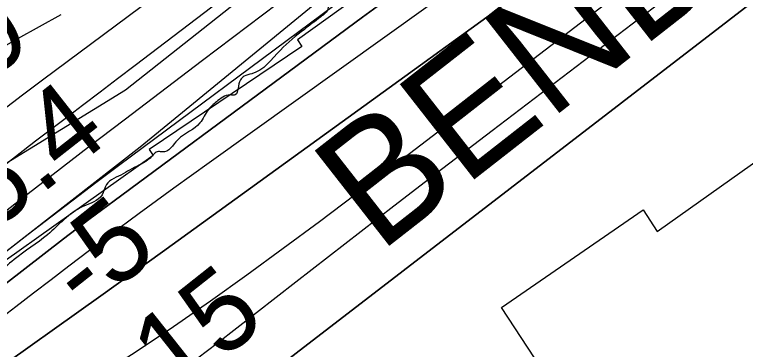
# Model space of a CAD drawing. Extents: x 3324104 to 3361979, y 612876 to 638273.
# Drawn here: x 3350527 to 3351130, y 619181 to 619458 of the extents above; entities that cross this region are included whole.
import ezdxf

# ---------------------------------------------------------------- set-up
doc = ezdxf.new("R2010")
doc.units = 0
for name, color, linetype in [('V-RIVR-EDGE', 7, 'Continuous'), ('V-RIVR-RANG', 7, 'Continuous'), ('V-RRAP-FSHR', 7, 'Continuous'), ('V-RRAP-RVMT', 7, 'Continuous'), ('V-RRAP-RVMT-IDEN', 7, 'Continuous'), ('V-TOPO-DPTH', 7, 'Continuous'), ('V-TOPO-MINR', 7, 'Continuous'), ('V-TOPO-WATR', 7, 'Continuous'), ('V-WETL-SWMP', 7, 'Continuous')]:
    doc.layers.add(name, color=color, linetype=linetype)

msp = doc.modelspace()

# ---------------------------------------------------------------- linework, layer by layer
at = {"layer": 'V-RIVR-EDGE'}
msp.add_spline([(3356051.95, 622889.63), (3356029.15, 622881.43), (3356012.46, 622875.66), (3355994.6, 622867.17), (3355977.52, 622859.07), (3355958.5, 622850.97), (3355948.4, 622843.24), (3355934.03, 622834.75), (3355904.12, 622817.76), (3355878.1, 622802.31), (3355856.74, 622790.34), (3355829.95, 622776.44), (3355805.11, 622765.65), (3355764.72, 622744.81), (3355744.14, 622733.61), (3355694.06, 622710.85), (3355668.43, 622698.12), (3355641.64, 622685), (3355605.15, 622669.19), (3355569.44, 622657.26), (3355539.17, 622646.47), (3355510.83, 622636.85), (3355482.11, 622628.39), (3355461.93, 622623.01), (3355442.52, 622614.14), (3355422.73, 622607.21), (3355409.53, 622603.36), (3355388.97, 622597.59), (3355371.88, 622589.49), (3355348.98, 622581.02), (3355297.71, 622547.02), (3355260.04, 622525.78), (3355211.1, 622494.49), (3355190.13, 622484.46), (3355184.7, 622482.92), (3355179.26, 622477.89), (3355174.21, 622475.58), (3355160.62, 622470.96), (3355143.54, 622463.63), (3355133.06, 622457.07), (3355125.67, 622450.49), (3355113.25, 622443.93), (3355096.93, 622433.11), (3355081.02, 622426.95), (3355064.32, 622419.23), (3355056.95, 622418.86), (3355048.8, 622414.62), (3355041.8, 622406.88), (3355036.76, 622406.5), (3355031.32, 622405.74), (3355027.05, 622404.2), (3355017.34, 622396.08), (3355010.74, 622394.93), (3355001.42, 622388.36), (3354988.6, 622379.09), (3354972.29, 622369.43), (3354947.44, 622356.31), (3354937.73, 622351.68), (3354926.08, 622343.56), (3354903.15, 622326.56), (3354891.11, 622318.06), (3354883.33, 622307.22), (3354879.44, 622304.12), (3354875.17, 622302.58), (3354867.8, 622299.11), (3354853.03, 622288.29), (3354842.54, 622279.01), (3354826.61, 622267.41), (3354807.2, 622259.71), (3354793.23, 622255.47), (3354765.68, 622249.73), (3354748.61, 622245.5), (3354734.63, 622239.33), (3354712.11, 622227.37), (3354697.74, 622218.87), (3354685.31, 622209.98), (3354640.65, 622184.5), (3354622.01, 622176.01), (3354616.19, 622175.25), (3354603.38, 622167.52), (3354578.92, 622157.11), (3354554.46, 622147.48), (3354537.39, 622142.87), (3354530.78, 622137.84), (3354500.11, 622122.79), (3354463.61, 622102.33), (3354417.79, 622078.79), (3354386.33, 622060.64), (3354340.11, 622032.44), (3354321.08, 622021.25), (3354284.96, 621998.84), (3354257, 621982.24), (3354217, 621958.68), (3354194.08, 621942.84), (3354176.99, 621931.63), (3354157.57, 621921.98), (3354141.64, 621910.39), (3354135.42, 621904.2), (3354130.36, 621897.62), (3354120.65, 621891.05), (3354103.96, 621882.95), (3354075.58, 621856.65), (3354044.89, 621835.39), (3354013.04, 621812.21), (3353971.47, 621781.67), (3353947.77, 621763.5), (3353941.17, 621763.52), (3353935.35, 621762.76), (3353929.53, 621760.06), (3353924.87, 621756.58), (3353920.59, 621751.55), (3353917.08, 621742.64), (3353910.48, 621741.49), (3353904.66, 621738.4), (3353893.78, 621731.06), (3353879.8, 621721.4), (3353866.19, 621708.64), (3353854.92, 621697.42), (3353843.26, 621687.75), (3353839.77, 621688.54), (3353831.23, 621686.23), (3353823.08, 621681.21), (3353818.03, 621677.34), (3353800.94, 621666.14), (3353790.85, 621663.06), (3353781.91, 621654.94), (3353777.63, 621651.85), (3353776.07, 621648.75), (3353775.67, 621643.71), (3353772.18, 621641), (3353755.87, 621632.13), (3353735.68, 621622.09), (3353718.58, 621608.17), (3353704.21, 621600.45), (3353694.12, 621596.6), (3353683.64, 621592.36), (3353671.21, 621584.25), (3353642.07, 621562.99), (3353598.95, 621534.01), (3353578.37, 621522.43), (3353556.23, 621507.75), (3353547.68, 621501.95), (3353525.93, 621489.21), (3353513.12, 621481.09), (3353497.18, 621468.34), (3353476.98, 621450.94), (3353453.28, 621436.65), (3353435.8, 621424.67), (3353404.72, 621401.09), (3353378.3, 621380.21), (3353361.59, 621368.62), (3353339.46, 621355.1), (3353319.65, 621342.35), (3353299.45, 621329.99), (3353283.54, 621324.6), (3353273.05, 621317.65), (3353254.77, 621295.98), (3353236.88, 621275.47), (3353219.39, 621258.83), (3353195.69, 621241.44), (3353168.49, 621221.34), (3353137.81, 621201.64), (3353112.17, 621185.03), (3353065.55, 621151.79), (3353022.05, 621122.82), (3352993.29, 621100.39), (3352956, 621073.34), (3352907.05, 621037.78), (3352853.8, 620991.77), (3352787.76, 620942.29), (3352749.68, 620913.3), (3352736.85, 620900.92), (3352733.34, 620892.79), (3352728.67, 620886.59), (3352718.96, 620881.19), (3352691.78, 620864.58), (3352660.31, 620841.78), (3352640.5, 620828.25), (3352623.39, 620811.23), (3352605.12, 620792.27), (3352593.46, 620783), (3352582.59, 620778.76), (3352566.29, 620771.43), (3352548.04, 620764.49), (3352522.41, 620750.98), (3352494.45, 620735.54), (3352482.41, 620727.04), (3352479.3, 620723.17), (3352476.96, 620717.36), (3352470.74, 620711.94), (3352455.99, 620707.33), (3352443.18, 620700.38), (3352419.1, 620685.7), (3352392.3, 620669.09), (3352362.78, 620650.94), (3352339.08, 620634.32), (3352315.38, 620615.38), (3352284.68, 620590.63), (3352258.65, 620571.31), (3352228.74, 620550.05), (3352193.39, 620527.65), (3352156.88, 620504.86), (3352131.63, 620487.47), (3352093.95, 620462.36), (3352049.28, 620432.99), (3351990.23, 620391.26), (3351936.63, 620357.26), (3351851.55, 620293.87), (3351833.29, 620281.51), (3351816.98, 620273.79), (3351794.06, 620257.95), (3351767.65, 620240.95), (3351719.86, 620206.17), (3351680.63, 620177.57), (3351657.32, 620160.56), (3351637.11, 620145.87), (3351623.13, 620135.44), (3351603.32, 620124.24), (3351588.57, 620120.01), (3351567.22, 620109.59), (3351552.08, 620103.43), (3351538.1, 620096.48), (3351523.73, 620086.43), (3351510.91, 620076.38), (3351503.52, 620069.81), (3351495.35, 620057.42), (3351486, 620042.32), (3351479.39, 620032.64), (3351469.67, 620022.58), (3351448.3, 620006.34), (3351431.59, 619994.75), (3351404.78, 619973.88), (3351377.97, 619951.84), (3351358.93, 619936.37), (3351332.12, 619915.5), (3351306.08, 619892.29), (3351274.58, 619858.25), (3351238.83, 619826.92), (3351215.12, 619805.65), (3351171.59, 619767.75), (3351145.54, 619739.51), (3351124.55, 619722.11), (3351105.9, 619707.81), (3351089.59, 619696.99), (3351079.49, 619691.2), (3351074.04, 619683.45), (3351058.1, 619666.43), (3351043.34, 619655.22), (3351015.36, 619633.96), (3350999.05, 619623.14), (3350992.05, 619617.34), (3350979.23, 619606.13), (3350966.01, 619594.53), (3350951.25, 619582.15), (3350935.7, 619567.84), (3350923.26, 619555.08), (3350910.05, 619544.25), (3350888.29, 619528.02), (3350846.74, 619504.08), (3350821.49, 619490.18), (3350811.39, 619483.61), (3350805.96, 619480.52), (3350800.9, 619473.16), (3350797.41, 619473.17), (3350793.92, 619474.35), (3350788.88, 619473.58), (3350786.93, 619472.04), (3350785.37, 619467.39), (3350785.36, 619462.73), (3350779.53, 619456.15), (3350765.93, 619445.72), (3350746.11, 619428.7), (3350722.4, 619408.98), (3350716.19, 619407.06), (3350713.08, 619403.96), (3350711.13, 619396.99), (3350708.79, 619391.57), (3350704.52, 619391.58), (3350693.26, 619385.79), (3350686.65, 619379.6), (3350679.64, 619368.37), (3350661.38, 619354.45), (3350648.56, 619344.4), (3350645.46, 619344.8), (3350638.47, 619339.39), (3350623.32, 619330.5), (3350616.33, 619326.26), (3350602.35, 619317.37), (3350598.83, 619308.85), (3350582.91, 619299.19), (3350553.77, 619276), (3350526.18, 619255.51), (3350493.55, 619231.94), (3350474.9, 619219.57), (3350474.5, 619213.76), (3350470.22, 619207.17), (3350458.96, 619202.55), (3350446.14, 619194.05), (3350441.09, 619189.79), (3350438.76, 619186.31), (3350434.48, 619180.89), (3350414.67, 619167.76), (3350401.46, 619159.26), (3350384.75, 619146.89), (3350369.6, 619133.74), (3350356.39, 619125.24), (3350350.95, 619119.05), (3350347.43, 619109.36), (3350338.1, 619097.75), (3350324.88, 619083.82), (3350308.55, 619069.9), (3350300.39, 619062.56), (3350296.13, 619062.57), (3350291.47, 619062.19), (3350274.77, 619050.6), (3350258.45, 619037.45), (3350251.84, 619032.81), (3350244.08, 619029.34), (3350233.61, 619028.21), (3350227.39, 619024.34), (3350220.39, 619016.99), (3350213, 619007.32), (3350202.12, 618996.87), (3350193.57, 618989.52), (3350179.6, 618985.29), (3350173.77, 618980.65), (3350164.84, 618977.96), (3350162.12, 618975.25), (3350159.39, 618971.38), (3350154.33, 618963.64), (3350145.78, 618953.19), (3350125.96, 618938.11), (3350102.66, 618923.05), (3350094.5, 618918.41), (3350086.34, 618913), (3350075.07, 618901.01), (3350064.19, 618892.12), (3350039.32, 618873.57), (3350021.84, 618861.59), (3350002.03, 618848.84), (3349991.94, 618844.21), (3349964.36, 618826.44), (3349938.72, 618807.11), (3349915.41, 618792.82), (3349892.5, 618778.92), (3349868.02, 618761.91), (3349852.49, 618753.03), (3349842.79, 618749.95), (3349830.35, 618739.13), (3349804.32, 618720.19), (3349777.9, 618697.76), (3349751.86, 618677.66), (3349729.72, 618661.43), (3349703.69, 618642.88), (3349678.84, 618629.75), (3349648.93, 618611.99), (3349624.46, 618594.99), (3349592.61, 618575.67), (3349570.48, 618564.87), (3349549.5, 618548.63), (3349505.21, 618518.11), (3349479.19, 618499.94), (3349471.42, 618494.53), (3349458.99, 618487.59), (3349438.4, 618472.12), (3349412.37, 618452.41), (3349379.73, 618429.61), (3349350.21, 618410.29), (3349303.2, 618374.73), (3349277.56, 618357.73), (3349263.97, 618347.29), (3349241.43, 618330.68), (3349226.67, 618319.85), (3349207.25, 618306.33), (3349193.17, 618293.54)], degree=3, dxfattribs=at)
at = {"layer": 'V-RRAP-FSHR'}
msp.add_lwpolyline([(3349156.55, 618293.48), (3349290.84, 618378.98), (3349409.37, 618477.79), (3349541.25, 618565.26), (3349771.64, 618715.9), (3349922.45, 618808.45), (3350215.79, 619019.76), (3350269.12, 619069.35), (3350501.35, 619248.31), (3350630.24, 619348.58), (3350981.59, 619636.83), (3351335.34, 619937.32), (3351550.69, 620108.65), (3351713.66, 620224.46), (3351812.36, 620304.63), (3352053.37, 620458.3), (3352414.71, 620728.03), (3352590.48, 620825.76), (3352682.34, 620894.14), (3352964.07, 621108.39), (3353211.76, 621284.79), (3354078.79, 621880.27)], dxfattribs=at)
at = {"layer": 'V-RRAP-RVMT'}
for p, q in [((3350883.62, 619526.25), (3350760.32, 619437.08)), ((3350760.32, 619437.08), (3350763.97, 619431.57)), ((3350763.97, 619431.57), (3350637.61, 619346.46)), ((3351057.33, 619278.7), (3351187.65, 619371.34)), ((3350637.61, 619346.46), (3350641.14, 619341.39)), ((3350641.14, 619341.39), (3350517.87, 619253.93)), ((3350928.77, 619215.7), (3351045.8, 619296.63)), ((3351045.8, 619296.63), (3351057.33, 619278.7)), ((3350956.08, 619174.07), (3350928.77, 619215.7))]:
    msp.add_line(p, q, dxfattribs=at)
at = {"layer": 'V-TOPO-DPTH'}
for points in [[(3350500.92, 619156.58), (3350597.73, 619225.34), (3350610.48, 619234.42), (3350623.21, 619243.52), (3350635.92, 619252.67), (3350648.6, 619261.84), (3350950.63, 619480.72), (3350989.67, 619509.08), (3351028.67, 619537.5), (3351067.61, 619566.01), (3351106.5, 619594.57), (3351173.35, 619643.79), (3351178.79, 619647.79), (3351184.23, 619651.79), (3351189.67, 619655.78), (3351195.12, 619659.76), (3351280.51, 619722.16), (3351328.59, 619757.43), (3351376.59, 619792.82), (3351424.45, 619828.38), (3351472.23, 619864.06), (3351729.95, 620057.28), (3351738.1, 620063.46)], [(3351738.1, 620063.46), (3351729.95, 620057.28), (3351472.23, 619864.06), (3351424.45, 619828.38), (3351376.59, 619792.82), (3351328.59, 619757.43), (3351280.51, 619722.16), (3351195.12, 619659.76), (3351189.67, 619655.78), (3351184.23, 619651.79), (3351178.79, 619647.79), (3351173.35, 619643.79), (3351106.5, 619594.57), (3351067.61, 619566.01), (3351028.67, 619537.5), (3350989.67, 619509.08), (3350950.63, 619480.72), (3350648.6, 619261.84), (3350635.92, 619252.67), (3350623.21, 619243.52), (3350610.48, 619234.42), (3350597.73, 619225.34), (3350500.92, 619156.58)], [(3351793.38, 619988), (3351727.81, 619942.08), (3351689.08, 619915.01), (3351650.31, 619887.99), (3351611.5, 619861.05), (3351572.65, 619834.15), (3351261.99, 619619.54), (3351244.52, 619607.29), (3351227.16, 619594.86), (3351209.99, 619582.2), (3351192.93, 619569.36), (3350921.06, 619361.8), (3350880.42, 619330.68), (3350839.84, 619299.48), (3350799.34, 619268.16), (3350758.91, 619236.77), (3350693.86, 619186.11), (3350685.96, 619180.04), (3350678, 619174.03), (3350669.98, 619168.12), (3350661.9, 619162.28), (3350597.95, 619116.62), (3350557.59, 619088.4), (3350516.88, 619060.72)], [(3351793.38, 619988), (3351727.81, 619942.08), (3351689.08, 619915.01), (3351650.31, 619887.99), (3351611.5, 619861.05), (3351572.65, 619834.15), (3351261.99, 619619.54), (3351244.52, 619607.29), (3351227.16, 619594.86), (3351209.99, 619582.2), (3351192.93, 619569.36), (3350921.06, 619361.8), (3350880.42, 619330.68), (3350839.84, 619299.48), (3350799.34, 619268.16), (3350758.91, 619236.77), (3350693.86, 619186.11), (3350685.96, 619180.04), (3350678, 619174.03), (3350669.98, 619168.12), (3350661.9, 619162.28), (3350597.95, 619116.62), (3350557.59, 619088.4), (3350516.88, 619060.72)], [(3350395.02, 618900.32), (3350654.07, 619097.36), (3350680.42, 619117.45), (3350706.75, 619137.57), (3350733.03, 619157.75), (3350759.29, 619177.96), (3351204.77, 619521.59), (3351212.95, 619527.9), (3351221.15, 619534.2), (3351229.35, 619540.49), (3351237.56, 619546.77), (3351245.83, 619552.97), (3351254.18, 619559.06), (3351262.63, 619565), (3351271.17, 619570.83), (3351275.85, 619573.96), (3351286.77, 619581.29), (3351297.7, 619588.61), (3351308.62, 619595.94), (3351319.54, 619603.27), (3351781.82, 619913.5)], [(3350686.93, 619122.42), (3350706.75, 619137.57), (3350733.03, 619157.75), (3350759.29, 619177.96), (3351204.77, 619521.59), (3351212.95, 619527.9), (3351221.15, 619534.2), (3351229.35, 619540.49), (3351237.56, 619546.77), (3351245.83, 619552.97), (3351254.18, 619559.06), (3351262.63, 619565), (3351271.17, 619570.83), (3351275.85, 619573.96), (3351286.77, 619581.29), (3351297.7, 619588.61), (3351308.62, 619595.94), (3351319.54, 619603.27), (3351781.82, 619913.5)], [(3351138.82, 619767.79), (3351112.25, 619747.19), (3351085.59, 619726.7), (3351058.86, 619706.3), (3350929.33, 619607.82), (3350867.49, 619560.83), (3350805.64, 619513.85), (3350743.78, 619466.88), (3350681.91, 619419.93), (3350616.98, 619370.66), (3350587.62, 619348.28), (3350558.34, 619325.79), (3350529.16, 619303.17), (3350500.06, 619280.45)], [(3350452.43, 619183.86), (3350567.04, 619272.57), (3350577.39, 619280.53), (3350587.78, 619288.45), (3350598.22, 619296.29), (3350608.7, 619304.1), (3350747.32, 619406.64), (3350813.93, 619455.73), (3350880.66, 619504.68), (3350947.55, 619553.39), (3351014.55, 619601.95), (3351126.37, 619682.68), (3351137.53, 619690.79)], [(3350452.43, 619183.86), (3350567.04, 619272.57), (3350577.39, 619280.53), (3350587.78, 619288.45), (3350598.22, 619296.29), (3350608.7, 619304.1), (3350747.32, 619406.64), (3350813.93, 619455.73), (3350880.66, 619504.68), (3350947.55, 619553.39), (3351014.55, 619601.95), (3351126.37, 619682.68), (3351137.53, 619690.79)]]:
    msp.add_lwpolyline(points, dxfattribs=at)
at = {"layer": 'V-TOPO-MINR'}
for points in [[(3351976.54, 620483.42), (3351682.77, 620260.49), (3351654.84, 620239.27), (3351626.94, 620218.02), (3351599.06, 620196.74), (3351571.2, 620175.44), (3351141.24, 619846.18), (3351130.29, 619837.79), (3351119.35, 619829.4), (3351108.4, 619821), (3351097.46, 619812.6), (3351080.44, 619799.52), (3351078.01, 619797.66), (3351075.57, 619795.81), (3351073.13, 619793.96), (3351070.68, 619792.13), (3351038.59, 619768.12), (3351020.09, 619754.29), (3351001.59, 619740.46), (3350983.07, 619726.65), (3350964.55, 619712.85), (3350549.5, 619403.67), (3350533.02, 619391.24), (3350516.63, 619378.69)], [(3351747.23, 620194.54), (3351715.65, 620170.75), (3351684.14, 620146.86), (3351652.76, 620122.82), (3351621.44, 620098.67), (3351144.46, 619728.99), (3351142.51, 619727.48), (3351140.56, 619725.99), (3351136.65, 619723.01), (3351133.13, 619720.35), (3351132.32, 619719.75), (3351131.91, 619719.45), (3351127.59, 619716.3), (3351125.02, 619714.42), (3351122.46, 619712.54), (3351119.9, 619710.65), (3351117.34, 619708.76), (3350612.45, 619332.91), (3350593.69, 619318.84), (3350574.98, 619304.68), (3350556.37, 619290.4), (3350537.82, 619276.04), (3350162.62, 618983.47)], [(3351738.1, 620063.46), (3351729.95, 620057.28), (3351472.23, 619864.06), (3351424.45, 619828.38), (3351376.59, 619792.82), (3351328.59, 619757.43), (3351280.51, 619722.16), (3351195.12, 619659.76), (3351189.67, 619655.78), (3351184.23, 619651.79), (3351178.79, 619647.79), (3351173.35, 619643.79), (3351106.5, 619594.57), (3351067.61, 619566.01), (3351028.67, 619537.5), (3350989.67, 619509.08), (3350950.63, 619480.72), (3350648.6, 619261.84), (3350635.92, 619252.67), (3350623.21, 619243.52), (3350610.48, 619234.42), (3350597.73, 619225.34), (3350500.92, 619156.58)], [(3351750.98, 619999.25), (3351718.07, 619975.66), (3351672.34, 619943.41), (3351616.38, 619903.92), (3351560.44, 619864.41), (3351504.52, 619824.88), (3351448.61, 619785.33), (3351267.51, 619657.16), (3351239.15, 619636.86), (3351210.96, 619616.35), (3351182.99, 619595.52), (3351155.18, 619574.48), (3350837.56, 619331.38), (3350807.99, 619308.91), (3350778.31, 619286.58), (3350748.47, 619264.47), (3350718.53, 619242.5), (3350688.31, 619220.94), (3350657.8, 619199.78), (3350626.89, 619179.23), (3350595.69, 619159.09), (3350255.13, 618943.95)], [(3351793.38, 619988), (3351727.81, 619942.08), (3351689.08, 619915.01), (3351650.31, 619887.99), (3351611.5, 619861.05), (3351572.65, 619834.15), (3351261.99, 619619.54), (3351244.52, 619607.29), (3351227.16, 619594.86), (3351209.99, 619582.2), (3351192.93, 619569.36), (3350921.06, 619361.8), (3350880.42, 619330.68), (3350839.84, 619299.48), (3350799.34, 619268.16), (3350758.91, 619236.77), (3350693.86, 619186.11), (3350685.96, 619180.04), (3350678, 619174.03), (3350669.98, 619168.12), (3350661.9, 619162.28), (3350597.95, 619116.62), (3350557.59, 619088.4), (3350516.88, 619060.72)], [(3351781.82, 619913.5), (3351319.54, 619603.27), (3351308.62, 619595.94), (3351297.7, 619588.61), (3351286.77, 619581.29), (3351275.85, 619573.96), (3351271.17, 619570.83), (3351262.63, 619565), (3351254.18, 619559.06), (3351245.83, 619552.97), (3351237.56, 619546.77), (3351229.35, 619540.49), (3351221.15, 619534.2), (3351212.95, 619527.9), (3351204.77, 619521.59), (3350759.29, 619177.96), (3350733.03, 619157.75), (3350706.75, 619137.57), (3350680.42, 619117.45), (3350654.07, 619097.36), (3350395.02, 618900.32)], [(3351217.59, 619868.07), (3351121.83, 619794), (3351107.64, 619783.05), (3351093.44, 619772.12), (3351079.22, 619761.23), (3351064.98, 619750.35), (3350626.08, 619415.92), (3350611.63, 619404.91), (3350597.18, 619393.9), (3350582.73, 619382.89), (3350568.28, 619371.87), (3350542.68, 619352.37), (3350541.03, 619351.1), (3350537.74, 619348.56), (3350536.11, 619347.28), (3350519.84, 619334.5)], [(3351138.82, 619767.79), (3351112.25, 619747.19), (3351085.59, 619726.7), (3351058.86, 619706.3), (3350929.33, 619607.82), (3350867.49, 619560.83), (3350805.64, 619513.85), (3350743.78, 619466.88), (3350681.91, 619419.93), (3350616.98, 619370.66), (3350587.62, 619348.28), (3350558.34, 619325.79), (3350529.16, 619303.17), (3350500.06, 619280.45)], [(3351142.68, 619661.91), (3351120.72, 619646.07), (3350687.16, 619335.37), (3350672.66, 619324.94), (3350658.19, 619314.47), (3350643.76, 619303.95), (3350629.35, 619293.39), (3350604.86, 619275.38), (3350602.72, 619273.8), (3350600.59, 619272.21), (3350598.47, 619270.6), (3350596.35, 619268.99), (3350571.42, 619249.85), (3350556.82, 619238.67), (3350542.21, 619227.52), (3350527.58, 619216.4), (3350512.93, 619205.3)]]:
    msp.add_lwpolyline(points, dxfattribs=at)
at = {"layer": 'V-TOPO-WATR'}
msp.add_lwpolyline([(3351137.53, 619690.79), (3351126.37, 619682.68), (3351014.55, 619601.95), (3350947.55, 619553.39), (3350880.66, 619504.68), (3350813.93, 619455.73), (3350747.32, 619406.64), (3350608.7, 619304.1), (3350598.22, 619296.29), (3350587.78, 619288.45), (3350577.39, 619280.53), (3350567.04, 619272.57), (3350452.43, 619183.86)], dxfattribs=at)
at = {"layer": 'V-WETL-SWMP'}
for p, q in [((3350752.72, 619502.11), (3350618.02, 619395.63)), ((3350547.01, 619448.23), (3350564.95, 619457.99)), ((3350529.17, 619438.3), (3350547.01, 619448.23)), ((3350511.42, 619428.2), (3350529.17, 619438.3)), ((3350618.02, 619395.63), (3350452.74, 619293.77))]:
    msp.add_line(p, q, dxfattribs=at)

# ---------------------------------------------------------------- texts
at = {"layer": 'V-RIVR-RANG'}
for s, rotation, p in [('25.9', 38.10833, (3350407.11, 619325.33)), ('15.4', 38.10833, (3350469.23, 619246.96)), ('-5', 38.39558, (3350584.78, 619210.18)), ('-15', 38.39558, (3350634.7, 619122.15))]:
    msp.add_text(s, height=67, rotation=rotation, dxfattribs=at).set_placement(p)
at = {"layer": 'V-RRAP-RVMT-IDEN'}
msp.add_text('BEND', height=100, rotation=38.01766, dxfattribs=at).set_placement((3350827.47, 619260.01))

doc.saveas('drawing.dxf')
